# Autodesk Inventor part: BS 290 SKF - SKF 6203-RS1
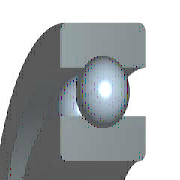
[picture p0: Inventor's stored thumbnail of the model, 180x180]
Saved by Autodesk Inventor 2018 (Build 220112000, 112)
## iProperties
Created: 2017-02
Part Number: BS 290 SKF - SKF 6203-RS1
Material: Steel, Mild
Description: Deep groove ball bearings single row with RS1 seal SKF
Document SubType Name: Modeling
Standard: BS 290 SKF
Designer: formation
Standards Organization: BSI
Language: en-US
Size Designation: SKF 6203-RS1
Categories: <MemberInstance><Categories><Category DisplayName="Shaft Parts" InternalName="7f7aeb1f-a693-4053-b835-cee3144e0d98" Mnemonic="SHFT"><Category DisplayName="Beari
Density: 7.85 g/cm^3
Appearance: Semi-Polished
IsCustomPart: 0
Author: formation
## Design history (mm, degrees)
node "Sketch1"
node "WorkPoint1"
node "WorkAxis1"
node "WorkPlane3"
node "WorkPlane4"
node "Sketch4"
node "WorkPoint2"
pattern_circular "PolarArray1" dims "d17" = 65.95652 (= msp_pocet), angle "d19" = 360 deg
fillet "Fillet1" dims "d20" = 0.6 (= r)
body "Solid1"
revolve "Revolution1" stored, may be unused: angle "d6" = 360 deg
revolve "Revolution2" stored, may be unused: angle "d10" = 360 deg
revolve "Revolution3" stored, may be unused: angle "d16" = 360 deg
sketch "Sketch2"
  geometry: L1 (8.5, 12)-(20, 12); L2 (8.5, 0)-(8.5, 12); L3 (20, 0)-(8.5, 0); L4 (20, 12)-(20, 0); L5 (0, 0)-(0, 20); L6 (0, 0)-(0, 20); L7 (-7.2, 0)-(43.2, 0) reference
  constraints: 12 end point, 3 vertical, 2 horizontal, 1 collinear, 1 other
  dimensions: "d1" = 17 diameter of L1.start L5 (= Diam); "d3" = 40 diameter of L1.end L5 (= DD); "d5" = 12 distance of L2.start L1.start (= msp_mdtd2)
sketch "Sketch3"
  geometry: L1 (16.32, 12)-(16.32, 8.76); L2 (12.18, 12)-(16.32, 12); L3 (12.18, 8.76)-(12.18, 12); L4 (12.18, 0)-(12.18, 3.24); L5 (16.32, 0)-(12.18, 0); L6 (16.32, 3.24)-(16.32, 0); L7 (20, 0)-(-20, 0) reference; L8 (20, 12)-(-20, 12) reference; L9 (0, -42.29)-(0, 61.29); L10 (0, 82.007)-(0, -63.007) reference; A1 r 3.45 centre (14.25, 6) between (16.32, 3.24) and (16.32, 8.76); A2 r 3.45 centre (14.25, 6) between (12.18, 8.76) and (12.18, 3.24)
  constraints: 14 end point, 4 collinear, 4 point on circle, 4 vertical, 2 centre point, 2 concentric, 2 horizontal, 2 point on line
  dimensions: "d9" = 6.9 diameter of A1 (= msp_mdtd6); "d21" = 12.18 distance between parallel lines of L9 L4 (= 0.5 x msp_d1); "d22" = 14.25 distance from line of L9 A1.centre (= 0.5 x msp_ds); "d23" = 16.32 distance between parallel lines of L9 L6 (= 0.5 x msp_dd1)
sketch "Sketch5"
  geometry: L1 (14.25, 2.55)-(14.25, 9.45); L2 (16.32, 0)-(-16.32, 0) reference; L3 (14.25, 2.55)-(14.25, 9.45); A1 r 3.45 centre (14.25, 6) between (14.25, 2.55) and (14.25, 9.45); A2 r 3.45 centre (14.25, 6) between (16.32, 3.24) and (16.32, 8.76) reference
  constraints: 4 end point, 2 point on circle, 1 centre point, 1 concentric, 1 vertical
  dimensions: "d13" = 0 horizontal distance of A1.centre L1.start; "d15" = 6.9001 diameter of A1 (computed from msp_mdtd6)
other parameters: "Diam" = 17 [user parameter; used in 3 equation terms], "DD" = 40 [user parameter; used in 3 equation terms], "B" = 12 [user parameter; used in 1 equation term], "r" = 0.6 [user parameter; used in 1 equation term], "msp_ds" = 28.5 (= 0.5 x Diam + 0.5 x DD) [user parameter; used in 5 equation terms], "msp_d0" = 6.9 (= -0.3 x Diam + 0.3 x DD) [user parameter; used in 4 equation terms], "msp_d1" = 24.36 (= msp_ds - 0.6 x msp_d0) [user parameter; used in 1 equation term], "msp_dd1" = 32.64 (= msp_ds + 0.6 x msp_d0) [user parameter; used in 1 equation term], "msp_pom" = 42.75 (= 1.5 x msp_ds) [user parameter; used in 1 equation term], "msp_mdtd2" = 12 (= B) [user parameter; used in 3 equation terms], "msp_mdtd4" = 28.5 (= msp_ds) [user parameter], "msp_mdtd6" = 6.9 (= msp_d0) [user parameter; used in 2 equation terms], "msp_mdtd7" = 6 (= 0.5 x msp_mdtd2) [user parameter], "msp_pocet" = 65.95652 (computed from msp_d0, msp_pom) [user parameter; used in 1 equation term], "d2" = 72 (derived), "d4" = 19 (derived), "d7" = 0, "d8" = 15.6 (derived), "d11" = -12 (computed from msp_mdtd2), "d12" = 0 (derived), "d14" = 15.6001 (derived), "d26" = 0, "d27" = 0, "d28" = 0, "d29" = 0, "d30" = 0
